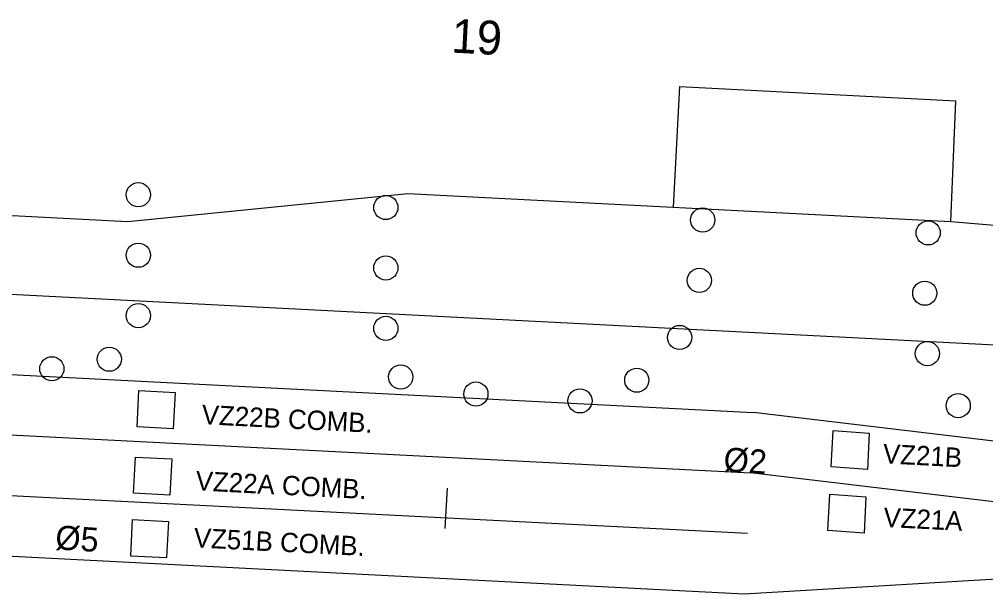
# Model space of a CAD drawing. Extents: x 0 to 1361828, y 0 to 1470398.
# Drawn here: x 681108.9 to 681268.7, y 735117.9 to 735212.9 of the extents above; entities that cross this region are included whole.
import ezdxf

# ---------------------------------------------------------------- set-up
doc = ezdxf.new("R2010")
doc.units = 0
for name, color, linetype in [('$', 7, 'Continuous'), ('MOT Stage 1', 7, 'Continuous'), ('MOT Stage 1 Lanes', 7, 'Continuous'), ('R_Horz Alg Station', 7, 'Continuous'), ('RW-EX', 7, 'Continuous'), ('RW-PR', 7, 'Continuous'), ('TITEXT', 7, 'Continuous'), ('Video-Zones-pr', 7, 'Continuous')]:
    doc.layers.add(name, color=color, linetype=linetype)

# ---------------------------------------------------------------- blocks, each defined once
blk = doc.blocks.new('BAREL_1498')
at = {"layer": 'MOT Stage 1'}
blk.add_circle((0, 0.01), 2.88, dxfattribs=at)
blk = doc.blocks.new('BAREL_1499')
at = {"layer": 'MOT Stage 1'}
blk.add_circle((0, 0.01), 2.88, dxfattribs=at)
blk = doc.blocks.new('BAREL_1500')
at = {"layer": 'MOT Stage 1'}
blk.add_circle((0, 0.01), 2.88, dxfattribs=at)
blk = doc.blocks.new('BAREL_1501')
at = {"layer": 'MOT Stage 1'}
blk.add_circle((0, 0.01), 2.88, dxfattribs=at)
blk = doc.blocks.new('BAREL_1502')
at = {"layer": 'MOT Stage 1'}
blk.add_circle((0, 0.01), 2.88, dxfattribs=at)
blk = doc.blocks.new('BAREL_1504')
at = {"layer": 'MOT Stage 1'}
blk.add_circle((0, 0.01), 2.88, dxfattribs=at)
blk = doc.blocks.new('BAREL_1505')
at = {"layer": 'MOT Stage 1'}
blk.add_circle((0, 0.01), 2.88, dxfattribs=at)
blk = doc.blocks.new('BAREL_1506')
at = {"layer": 'MOT Stage 1'}
blk.add_circle((0, 0.01), 2.88, dxfattribs=at)
blk = doc.blocks.new('BAREL_1507')
at = {"layer": 'MOT Stage 1'}
blk.add_circle((0, 0.01), 2.88, dxfattribs=at)
blk = doc.blocks.new('BAREL_1525')
at = {"layer": 'MOT Stage 1'}
blk.add_circle((0, 0.01), 2.88, dxfattribs=at)
blk = doc.blocks.new('BAREL_1527')
at = {"layer": 'MOT Stage 1'}
blk.add_circle((0, 0.01), 2.88, dxfattribs=at)
blk = doc.blocks.new('BAREL_1528')
at = {"layer": 'MOT Stage 1'}
blk.add_circle((0, 0.01), 2.88, dxfattribs=at)
blk = doc.blocks.new('BAREL_1535')
at = {"layer": 'MOT Stage 1'}
blk.add_circle((0, 0.01), 2.88, dxfattribs=at)
blk = doc.blocks.new('BAREL_1536')
at = {"layer": 'MOT Stage 1'}
blk.add_circle((0, 0.01), 2.88, dxfattribs=at)
blk = doc.blocks.new('BAREL_1537')
at = {"layer": 'MOT Stage 1'}
blk.add_circle((0, 0.01), 2.88, dxfattribs=at)
blk = doc.blocks.new('BAREL_1539')
at = {"layer": 'MOT Stage 1'}
blk.add_circle((0, 0.01), 2.88, dxfattribs=at)
blk = doc.blocks.new('BAREL_1540')
at = {"layer": 'MOT Stage 1'}
blk.add_circle((0, 0.01), 2.88, dxfattribs=at)
blk = doc.blocks.new('BAREL_1541')
at = {"layer": 'MOT Stage 1'}
blk.add_circle((0, 0.01), 2.88, dxfattribs=at)
blk = doc.blocks.new('BAREL_1542')
at = {"layer": 'MOT Stage 1'}
blk.add_circle((0, 0.01), 2.88, dxfattribs=at)

msp = doc.modelspace()

# ---------------------------------------------------------------- linework, layer by layer
at = {"layer": 'MOT Stage 1 Lanes'}
for p, q in [((681043.86, 735157.43), (681230.33, 735147.83)), ((681286.32, 735141.17), (681230.33, 735147.83)), ((681043.34, 735147.44), (681229.82, 735137.84)), ((681042.83, 735137.46), (681229.3, 735127.86)), ((681285.8, 735131.19), (681229.82, 735137.84)), ((681228.79, 735117.87), (681285.29, 735121.2))]:
    msp.add_line(p, q, dxfattribs=at)
msp.add_lwpolyline([(681042.86, 735157.48), (681041.31, 735127.52), (681228.79, 735117.87)], dxfattribs=at)
at = {"layer": 'R_Horz Alg Station'}
msp.add_lwpolyline([(681179.63, 735135.34), (681179.28, 735128.68)], dxfattribs=at)
at = {"layer": 'RW-EX'}
msp.add_line((681045.84, 735170.62), (681414.69, 735151.56), dxfattribs=at)
at = {"layer": 'RW-PR'}
for p, q in [((681217.07, 735181.8), (681218.11, 735201.77)), ((681218.11, 735201.77), (681263.79, 735199.41)), ((681262.96, 735179.43), (681263.79, 735199.41))]:
    msp.add_line(p, q, dxfattribs=at)
for points in [[(681052.81, 735200.3), (681076.9, 735182.04), (681126.83, 735179.45), (681173.16, 735184.07)], [(681173.16, 735184.07), (681262.96, 735179.43), (681415.52, 735166.6)]]:
    msp.add_lwpolyline(points, dxfattribs=at)
at = {"layer": 'Video-Zones-pr'}
for points in [[(681128.35, 735145.48), (681128.66, 735151.47), (681134.65, 735151.16), (681134.34, 735145.17)], [(681127.78, 735134.49), (681128.09, 735140.48), (681134.09, 735140.17), (681133.78, 735134.18)], [(681242.93, 735134.32), (681248.91, 735133.88), (681248.6, 735127.88), (681242.62, 735128.33)]]:
    msp.add_lwpolyline(points, close=True, dxfattribs=at)
for points in [[(681243.16, 735138.87), (681243.47, 735144.86), (681249.46, 735144.42), (681249.15, 735138.42), (681243.16, 735138.87)], [(681127.56, 735130.13), (681127.25, 735124.14)], [(681127.56, 735130.13), (681133.55, 735129.82)], [(681133.55, 735129.82), (681133.24, 735123.83)], [(681127.25, 735124.14), (681133.24, 735123.83)]]:
    msp.add_lwpolyline(points, dxfattribs=at)

# ---------------------------------------------------------------- block references
at = {"layer": 'MOT Stage 1', "xscale": 0.6945420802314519, "yscale": 0.6945420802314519, "rotation": 87.04179557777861}
for name, p in [('BAREL_1498', (681128.57, 735183.87)), ('BAREL_1504', (681169.51, 735181.76)), ('BAREL_1527', (681221.92, 735179.69)), ('BAREL_1528', (681259.2, 735177.56)), ('BAREL_1499', (681128.57, 735173.87)), ('BAREL_1505', (681169.51, 735171.76)), ('BAREL_1539', (681221.37, 735169.7)), ('BAREL_1535', (681258.64, 735167.58)), ('BAREL_1500', (681128.57, 735163.87)), ('BAREL_1506', (681169.51, 735161.76)), ('BAREL_1540', (681218.09, 735160.26)), ('BAREL_1501', (681123.77, 735156.66)), ('BAREL_1536', (681259.07, 735157.59)), ('BAREL_1502', (681114.27, 735155.08)), ('BAREL_1507', (681171.97, 735153.72)), ('BAREL_1541', (681211.01, 735153.19)), ('BAREL_1525', (681184.4, 735150.9)), ('BAREL_1542', (681201.61, 735149.77)), ('BAREL_1537', (681264.17, 735148.98))]:
    msp.add_blockref(name, p, dxfattribs=at)

# ---------------------------------------------------------------- texts
at = {"layer": '$'}
for s, height, rotation, p in [('19', 5.6, 357.0415, (681180.25, 735207.4)), ('VZ22B COMB.', 3.2, 357.065, (681138.99, 735145.93)), ('VZ21B', 3.2, 357.065, (681251.65, 735139.45)), ('VZ22A COMB.', 3.2, 357.065, (681137.99, 735134.97)), ('VZ21A', 3.2, 357.065, (681251.73, 735128.93)), ('VZ51B COMB.', 3.2, 357.065, (681137.68, 735125.55))]:
    msp.add_text(s, height=height, rotation=rotation, dxfattribs=at).set_placement(p)
at = {"layer": 'TITEXT'}
for s, p in [('%%C2', (681225.26, 735138.11)), ('%%C5', (681114.75, 735125.22))]:
    msp.add_text(s, height=4, rotation=356.2723, dxfattribs=at).set_placement(p)

doc.saveas('drawing.dxf')
